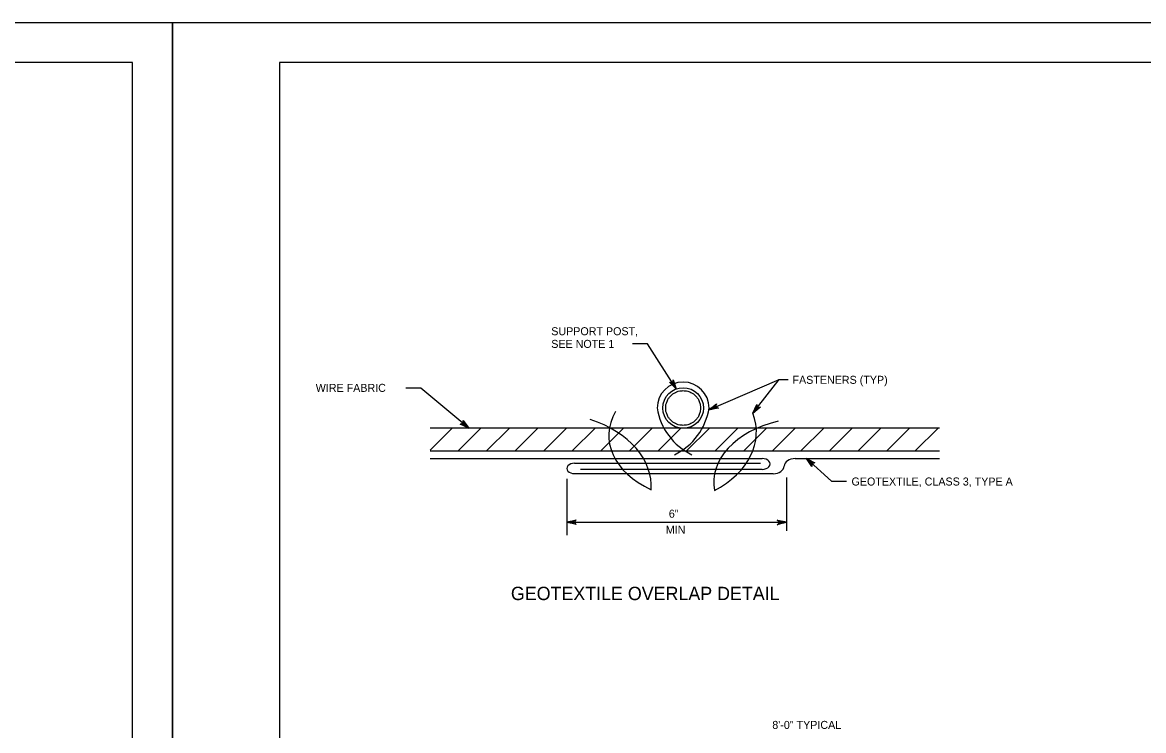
# Model space of a CAD drawing. Extents: x 636462 to 639049, y 299944 to 300538.
# Drawn here: x 637246.7 to 637666.6, y 300273.2 to 300538.4 of the extents above; entities that cross this region are included whole.
import ezdxf

# ---------------------------------------------------------------- set-up
doc = ezdxf.new("R2010")
doc.units = 0
for name, color, linetype in [('1', 7, 'Continuous'), ('Default', 7, 'Continuous'), ('PLT-BNDY', 7, 'Continuous')]:
    doc.layers.add(name, color=color, linetype=linetype)

msp = doc.modelspace()

# ---------------------------------------------------------------- linework, layer by layer
at = {"layer": '1'}
for points in [[(637287.91, 299959.45), (637287.91, 300523.45), (636501.91, 300523.45), (636501.91, 299959.45), (637287.91, 299959.45), (637287.91, 299985.81), (637087.91, 299985.81), (637087.91, 300050.49), (637287.91, 300050.49), (637287.91, 300079.45), (637087.91, 300079.45), (637087.91, 299959.45), (637166.72, 299959.45), (637166.72, 299985.81), (637166.72, 299959.45), (637243.72, 299959.45), (637243.72, 299985.81), (637243.72, 299973.49), (637287.91, 299973.49)], [(638128.91, 299959.45), (638128.91, 300523.45), (637342.91, 300523.45), (637342.91, 299959.45), (638128.91, 299959.45), (638128.91, 299985.81), (637928.91, 299985.81), (637928.91, 300050.49), (638128.91, 300050.49), (638128.91, 300079.45), (637928.91, 300079.45), (637928.91, 299959.45), (638007.72, 299959.45), (638007.72, 299985.81), (638007.72, 299959.45), (638084.72, 299959.45), (638084.72, 299985.81), (638084.72, 299973.49), (638128.91, 299973.49)]]:
    msp.add_lwpolyline(points, dxfattribs=at)
at = {"layer": 'Default'}
for p, q in [((637503.8, 300393.36), (637530.06, 300404.64)), ((637520.23, 300392.05), (637530.06, 300404.64)), ((637530.06, 300404.64), (637533.46, 300404.64)), ((637399.37, 300378.19), (637407.63, 300386.43)), ((637590.15, 300386.43), (637399.37, 300386.43)), ((637409.81, 300377.92), (637418.33, 300386.43)), ((637420.51, 300377.92), (637429.03, 300386.43)), ((637431.22, 300377.92), (637439.74, 300386.43)), ((637441.92, 300377.92), (637450.44, 300386.43)), ((637452.62, 300377.92), (637461.14, 300386.43)), ((637463.33, 300377.92), (637471.84, 300386.43)), ((637474.03, 300377.92), (637482.55, 300386.43)), ((637484.73, 300377.92), (637493.25, 300386.43)), ((637495.44, 300377.92), (637503.95, 300386.43)), ((637506.14, 300377.92), (637514.66, 300386.43)), ((637516.84, 300377.92), (637525.36, 300386.43)), ((637527.55, 300377.92), (637536.06, 300386.43)), ((637538.25, 300377.92), (637546.77, 300386.43)), ((637548.95, 300377.92), (637557.47, 300386.43)), ((637559.66, 300377.92), (637568.17, 300386.43)), ((637570.36, 300377.92), (637578.88, 300386.43)), ((637581.06, 300377.92), (637589.58, 300386.43)), ((637399.37, 300377.92), (637590.15, 300377.92)), ((637399.37, 300375.09), (637523.7, 300375.09)), ((637486.35, 300377.92), (637501.88, 300377.92)), ((637536.1, 300375.09), (637590.15, 300375.09)), ((637453.43, 300373.3), (637523.12, 300373.3)), ((637523.7, 300371.02), (637455.74, 300371.02)), ((637450.6, 300367.43), (637450.6, 300346.39)), ((637527.83, 300369.41), (637453.43, 300369.41)), ((637532.88, 300368.04), (637532.88, 300347.98))]:
    msp.add_line(p, q, dxfattribs=at)
for points in [[(637491.57, 300401.19), (637480.8, 300417.99), (637475.13, 300417.99)], [(637490.39, 300404.27), (637490.44, 300404.61), (637491.57, 300401.19), (637490.39, 300404.27), (637490.18, 300403.9), (637491.57, 300401.19), (637489.74, 300403.62), (637489.33, 300403.57), (637491.57, 300401.19), (637488.96, 300403.68), (637489.33, 300403.57)], [(637413.86, 300386.43), (637395.88, 300401.46), (637390.21, 300401.46)], [(637507.02, 300394.05), (637507.36, 300393.95), (637503.8, 300393.36), (637507.02, 300394.05), (637506.7, 300394.31), (637503.8, 300393.36), (637506.48, 300394.79), (637506.5, 300395.21), (637503.8, 300393.36), (637506.66, 300395.55), (637506.5, 300395.21)], [(637522.73, 300394.2), (637523.07, 300394.28), (637520.23, 300392.05), (637522.73, 300394.2), (637522.31, 300394.28), (637520.23, 300392.05), (637521.9, 300394.6), (637521.72, 300394.97), (637520.23, 300392.05), (637521.69, 300395.35), (637521.72, 300394.97)], [(637411.78, 300388.99), (637411.72, 300389.33), (637413.86, 300386.43), (637411.78, 300388.99), (637411.69, 300388.57), (637413.86, 300386.43), (637411.36, 300388.17), (637410.98, 300388), (637413.86, 300386.43), (637410.6, 300387.98), (637410.98, 300388)], [(637540.27, 300375.09), (637549.65, 300366.59), (637555.32, 300366.59)], [(637542.29, 300372.48), (637542.34, 300372.14), (637540.27, 300375.09), (637542.29, 300372.48), (637542.38, 300372.89), (637540.27, 300375.09), (637542.72, 300373.29), (637543.11, 300373.45), (637540.27, 300375.09), (637543.49, 300373.46), (637543.11, 300373.45)], [(637453.83, 300350.58), (637454.1, 300350.36), (637450.6, 300351.22), (637453.83, 300350.58), (637453.63, 300350.95), (637450.6, 300351.22), (637453.63, 300351.48), (637453.81, 300351.85), (637450.6, 300351.22), (637454.09, 300352.1), (637453.81, 300351.85)], [(637450.6, 300351.22), (637532.88, 300351.22)], [(637529.64, 300351.83), (637529.37, 300352.05), (637532.88, 300351.22), (637529.64, 300351.83), (637529.84, 300351.46), (637532.88, 300351.22), (637529.85, 300350.93), (637529.67, 300350.55), (637532.88, 300351.22), (637529.39, 300350.3), (637529.67, 300350.55)]]:
    msp.add_lwpolyline(points, dxfattribs=at)
for centre, radius, start, end in [((637494.11, 300394.01), 9.71, 90, 180), ((637494.11, 300394.01), 9.71, 0, 90), ((637507.41, 300397.51), 23.27, 188.6319, 244.4556), ((637480.82, 300397.51), 23.27, 295.5444, 351.3681)]:
    msp.add_arc(centre, radius, start, end, dxfattribs=at)
msp.add_ellipse((637494.11, 300394.01), major_axis=(7.62, 0), ratio=0.998811, dxfattribs=at)
for centre, major_axis, start_param, end_param in [((637501.64, 300383.65), (35.36, 0), 2.758937, 4.127507), ((637481.21, 300385.03), (40.35, 0), 5.368508, 6.539759), ((637441.82, 300364.8), (40.35, 0), 6.233289, 7.404541), ((637540.92, 300366.02), (35.36, 0), 1.894155, 3.262726), ((637523.7, 300373.05), (2.96, 0), 4.712389, 7.853982), ((637536.1, 300372.25), (-4.13, 0), 4.712389, 6.283185), ((637453.43, 300371.36), (-2.83, 0), 4.712389, 7.853982), ((637527.83, 300372.25), (4.13, 0), 4.712389, 6.283185)]:
    msp.add_ellipse(centre, major_axis=major_axis, ratio=0.686052, start_param=start_param, end_param=end_param, dxfattribs=at)
msp.add_open_spline([(637500.62, 300394.01), (637500.62, 300394.87), (637500.45, 300395.71), (637499.8, 300397.29), (637499.32, 300398.01), (637498.12, 300399.21), (637497.39, 300399.7), (637495.82, 300400.35), (637494.97, 300400.52), (637493.25, 300400.52), (637492.41, 300400.35), (637490.83, 300399.7), (637490.11, 300399.21), (637488.9, 300398.01), (637488.42, 300397.29), (637487.77, 300395.71), (637487.6, 300394.87), (637487.6, 300393.16), (637487.77, 300392.31), (637488.42, 300390.74), (637488.9, 300390.02), (637490.11, 300388.81), (637490.83, 300388.33), (637492.41, 300387.68), (637493.25, 300387.51), (637494.97, 300387.51), (637495.82, 300387.68), (637497.39, 300388.33), (637498.12, 300388.81), (637499.32, 300390.02), (637499.8, 300390.74), (637500.45, 300392.31), (637500.62, 300393.16), (637500.62, 300394.01)], degree=3, dxfattribs=at)
at = {"layer": 'PLT-BNDY'}
for points in [[(636461.91, 300538.45), (637302.91, 300538.45), (637302.91, 299944.45), (636461.91, 299944.45)], [(637302.91, 300538.45), (638143.91, 300538.45), (638143.91, 299944.45), (637302.91, 299944.45)]]:
    msp.add_lwpolyline(points, close=True, dxfattribs=at)

# ---------------------------------------------------------------- texts
at = {"layer": 'Default'}
for s, height, p in [('SUPPORT POST,', 2.998, (637444.73, 300421.27)), ('SEE NOTE 1', 2.998, (637444.73, 300416.53)), ('FASTENERS (TYP)', 2.998, (637535.08, 300403.07)), ('WIRE FABRIC', 2.998, (637356.52, 300400.06)), ('GEOTEXTILE, CLASS 3, TYPE A', 2.998, (637557.18, 300364.98)), ('6"', 2.998, (637488.76, 300352.91)), ('MIN', 2.998, (637487.63, 300346.92)), ('GEOTEXTILE OVERLAP DETAIL', 4.9967, (637429.61, 300322.05)), ('8\'-0" TYPICAL', 2.998, (637527.51, 300273.81))]:
    msp.add_text(s, height=height, dxfattribs=at).set_placement(p)

doc.saveas('drawing.dxf')
